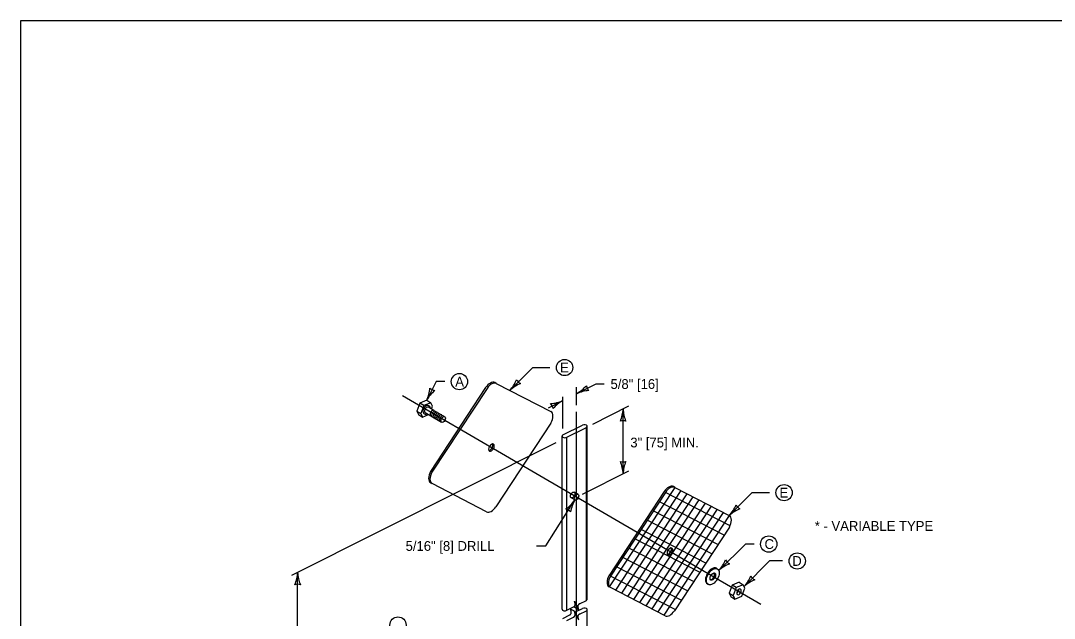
# Model space of a CAD drawing. Extents: x 49991.4 to 50021, y 49987.6 to 50011.4.
# Drawn here: x 49999.38 to 50005.73, y 49995.33 to 49999 of the extents above; entities that cross this region are included whole.
import ezdxf

# ---------------------------------------------------------------- set-up
doc = ezdxf.new("R2010")
doc.units = 0
for name, color, linetype in [('Level 1', 7, 'Continuous'), ('Level 2', 7, 'Continuous'), ('Level 25', 7, 'Continuous'), ('Level 3', 7, 'Continuous'), ('Level 4', 7, 'Continuous'), ('Level 5', 7, 'Continuous'), ('Level 6', 7, 'Continuous')]:
    doc.layers.add(name, color=color, linetype=linetype)

msp = doc.modelspace()

# ---------------------------------------------------------------- linework, layer by layer
at = {"layer": 'Level 1'}
for p, q in [((50002.2385, 49996.7445), (50001.9006, 49996.2299)), ((50002.2469, 49996.7397), (50001.9089, 49996.2251)), ((50002.3036, 49996.7701), (50002.2953, 49996.7749)), ((50002.3036, 49996.7701), (50002.6384, 49996.5971)), ((50001.8335, 49996.6484), (50001.8151, 49996.6003)), ((50001.8765, 49996.6664), (50001.8335, 49996.6484)), ((50001.8588, 49996.6336), (50001.8335, 49996.6484)), ((50001.8588, 49996.6336), (50001.8405, 49996.5855)), ((50001.9018, 49996.6516), (50001.8588, 49996.6336)), ((50001.8765, 49996.6664), (50001.9018, 49996.6516)), ((50001.921, 49996.6044), (50001.8874, 49996.6237)), ((50001.9123, 49996.6297), (50001.9018, 49996.6516)), ((50001.9059, 49996.613), (50001.9123, 49996.6297)), ((50001.921, 49996.6044), (50001.9876, 49996.5655)), ((50001.8151, 49996.6003), (50001.8256, 49996.5784)), ((50001.8151, 49996.6003), (50001.8405, 49996.5855)), ((50001.8256, 49996.5784), (50001.851, 49996.5636)), ((50001.8405, 49996.5855), (50001.851, 49996.5636)), ((50001.851, 49996.5636), (50001.887, 49996.5787)), ((50001.8666, 49996.5907), (50001.9013, 49996.5703)), ((50001.9013, 49996.5703), (50001.968, 49996.5316)), ((50002.6392, 49996.5265), (50002.3013, 49996.0119)), ((50002.7127, 49996.4535), (50002.8332, 49996.5141)), ((50002.7364, 49996.4397), (50002.857, 49996.5004)), ((50002.857, 49995.4366), (50002.857, 49996.5004)), ((50002.8619, 49995.4435), (50002.8619, 49996.5072)), ((50002.7077, 49995.3828), (50002.7077, 49996.4466)), ((50002.7364, 49995.376), (50002.7364, 49996.4397)), ((50001.9098, 49996.1545), (50001.9014, 49996.1593)), ((50002.2445, 49995.9815), (50001.9098, 49996.1545)), ((50003.3344, 49996.1056), (50002.9965, 49995.591)), ((50003.3995, 49996.1312), (50002.9979, 49995.5196)), ((50003.3428, 49996.1008), (50003.0048, 49995.5862)), ((50003.4367, 49996.112), (50003.0351, 49995.5004)), ((50003.7402, 49995.8954), (50003.3428, 49996.1008)), ((50003.3995, 49996.1312), (50003.7343, 49995.9582)), ((50003.4739, 49996.0927), (50003.0723, 49995.4812)), ((50003.5111, 49996.0735), (50003.1095, 49995.462)), ((50003.5483, 49996.0543), (50003.1467, 49995.4427)), ((50003.5855, 49996.0351), (50003.1839, 49995.4235)), ((50003.7027, 49995.8382), (50003.3052, 49996.0436)), ((50003.6227, 49996.0159), (50003.2211, 49995.4043)), ((50003.6599, 49995.9966), (50003.2583, 49995.3851)), ((50003.6651, 49995.7811), (50003.2677, 49995.9864)), ((50003.6971, 49995.9774), (50003.2955, 49995.3659)), ((50003.6276, 49995.7239), (50003.2301, 49995.9293)), ((50003.7343, 49995.9582), (50003.3327, 49995.3466)), ((50003.5901, 49995.6667), (50003.1926, 49995.8721)), ((50003.7351, 49995.8876), (50003.3972, 49995.373)), ((50003.5525, 49995.6095), (50003.155, 49995.8149)), ((50003.515, 49995.5523), (50003.1175, 49995.7577)), ((50003.4774, 49995.4952), (50003.0799, 49995.7005)), ((50003.4399, 49995.438), (50003.0424, 49995.6434)), ((50003.6549, 49995.6344), (50003.661, 49995.6309)), ((50003.4023, 49995.3808), (50003.0048, 49995.5862)), ((50003.6, 49995.5392), (50003.606, 49995.5356)), ((50003.7513, 49995.5303), (50003.733, 49995.4822)), ((50003.7943, 49995.5483), (50003.7513, 49995.5303)), ((50003.7767, 49995.5156), (50003.7513, 49995.5303)), ((50003.8197, 49995.5335), (50003.7767, 49995.5156)), ((50003.7943, 49995.5483), (50003.8197, 49995.5335)), ((50003.8302, 49995.5117), (50003.8197, 49995.5335)), ((50003.0057, 49995.5156), (50002.9973, 49995.5205)), ((50003.3404, 49995.3426), (50003.0057, 49995.5156)), ((50003.733, 49995.4822), (50003.7435, 49995.4603)), ((50003.733, 49995.4822), (50003.7584, 49995.4674)), ((50003.7767, 49995.5156), (50003.7584, 49995.4674)), ((50003.7584, 49995.4674), (50003.7689, 49995.4455)), ((50003.7689, 49995.4455), (50003.8119, 49995.4635)), ((50003.8119, 49995.4635), (50003.8302, 49995.5117)), ((50003.7435, 49995.4603), (50003.7689, 49995.4455)), ((50002.8619, 49992.2395), (50002.8619, 49995.3805))]:
    msp.add_line(p, q, dxfattribs=at)
msp.add_lwpolyline([(49999.3835, 49998.9992), (50016.7501, 49998.9992), (50016.7501, 49987.7988), (49999.3835, 49987.7988)], close=True, dxfattribs=at)
for centre, major_axis, ratio, start_param, end_param in [((50002.2657, 49996.7219), (0.0304, 0.0526), 0.57735, 0.026952, 1.471473), ((50002.2741, 49996.717), (0.0304, 0.0526), 0.57735, 0.026952, 1.471473), ((50001.8764, 49996.6076), (0.0145, 0.0251), 0.715069, 5.446271, 10.24969), ((50001.8764, 49996.6076), (0.0098, 0.0169), 0.57735, 6.151544, 9.424778), ((50001.9111, 49996.5874), (0.0098, 0.0169), 0.57735, 0.000016, 3.141596), ((50001.9207, 49996.5818), (0.0098, 0.0169), 0.57735, 0.000016, 3.141596), ((50001.9302, 49996.5763), (0.0098, 0.0169), 0.57735, 0.000016, 3.141596), ((50001.9397, 49996.5707), (0.0098, 0.0169), 0.57735, 0.000016, 3.141596), ((50001.9492, 49996.5652), (0.0098, 0.0169), 0.57735, 0.000016, 3.141596), ((50001.9587, 49996.5596), (0.0098, 0.0169), 0.57735, 0.000016, 3.141596), ((50001.9683, 49996.5541), (0.0098, 0.0169), 0.57735, 0.000016, 3.141596), ((50002.6088, 49996.544), (0.0304, 0.0526), 0.57735, 4.71239, 6.310148), ((50002.8451, 49996.5072), (0.0168, 0), 0.57735, 5.49777, 8.63937), ((50002.7245, 49996.4466), (0.0168, 0), 0.57735, 2.356185, 5.49777), ((50002.2741, 49996.3758), (0.0122, 0.0212), 0.57735, 3.153573, 9.424778), ((50002.2657, 49996.3806), (0.0122, 0.0212), 0.57735, 3.487866, 5.932002), ((50001.931, 49996.2124), (0.0304, 0.0526), 0.57735, 1.570791, 3.168563), ((50001.9393, 49996.2075), (0.0304, 0.0526), 0.57735, 1.570791, 3.168563), ((50003.3616, 49996.083), (0.0304, 0.0526), 0.57735, 0.026952, 1.471473), ((50003.37, 49996.0781), (0.0304, 0.0526), 0.57735, 0.026952, 1.471473), ((50002.2741, 49996.0346), (0.0304, 0.0526), 0.57735, 3.168548, 4.613061), ((50003.7047, 49995.9051), (0.0304, 0.0526), 0.57735, 4.71239, 6.310148), ((50003.37, 49995.7369), (0.0122, 0.0212), 0.57735, 3.153573, 9.424778), ((50003.3616, 49995.7418), (0.0122, 0.0212), 0.57735, 3.487866, 5.932002), ((50003.0269, 49995.5735), (0.0304, 0.0526), 0.57735, 1.570791, 3.168563), ((50003.6275, 49995.5868), (0.0275, 0.0476), 0.57735, 6.283184, 9.424776), ((50003.6275, 49995.5868), (0.0122, 0.0212), 0.57735, 3.391163, 6.028843), ((50003.0352, 49995.5687), (0.0304, 0.0526), 0.57735, 1.570791, 3.168563), ((50003.7943, 49995.4895), (0.0098, 0.0169), 0.57735, 3.147519, 9.423615), ((50003.78, 49995.4976), (0.0098, 0.0169), 0.57735, 3.961375, 5.478491), ((50003.7749, 49995.5008), (0.0098, 0.0169), 0.57735, 4.589945, 4.829787), ((50003.37, 49995.3957), (0.0304, 0.0526), 0.57735, 3.168548, 4.613061)]:
    msp.add_ellipse(centre, major_axis=major_axis, ratio=ratio, start_param=start_param, end_param=end_param, dxfattribs=at)
for centre, major_axis in [((50001.9778, 49996.5485), (0.0098, 0.0169)), ((50002.7967, 49996.0713), (0.0098, 0.0169)), ((50003.6335, 49995.5833), (0.0275, 0.0476)), ((50003.6335, 49995.5833), (0.0122, 0.0212))]:
    msp.add_ellipse(centre, major_axis=major_axis, ratio=0.57735, dxfattribs=at)
at = {"layer": 'Level 2'}
for centre in [(50002.7233, 49996.868), (50002.0775, 49996.7813), (50004.0709, 49996.099), (50003.9764, 49995.7831), (50004.1517, 49995.6792), (50001.7003, 49995.2856)]:
    msp.add_circle(centre, 0.05, dxfattribs=at)
at = {"layer": 'Level 25'}
for p, q in [((50002.7967, 49996.7072), (50002.881, 49996.7496)), ((50002.7967, 49996.7072), (50002.86, 49996.7391)), ((50003.3995, 49996.1312), (50003.3912, 49996.136)), ((50003.661, 49995.6309), (50003.6549, 49995.6344)), ((50003.606, 49995.5356), (50003.6, 49995.5392)), ((50002.7967, 49995.3434), (50002.7967, 49995.4063))]:
    msp.add_line(p, q, dxfattribs=at)
at = {"layer": 'Level 3'}
for p, q in [((50002.7967, 49996.6357), (50002.7967, 49996.7472)), ((50002.7126, 49996.4935), (50002.7126, 49996.6873)), ((50002.6244, 49996.6206), (50002.7126, 49996.665)), ((50002.8976, 49996.5208), (50003.1183, 49996.6317)), ((50003.0825, 49996.215), (50003.0825, 49996.6137)), ((50001.0489, 49995.5917), (50002.6719, 49996.4074)), ((50002.8322, 49996.0892), (50003.1183, 49996.233)), ((50001.084, 49993.6606), (50001.084, 49995.6093))]:
    msp.add_line(p, q, dxfattribs=at)
for points in [[(50002.3867, 49996.7271), (50002.528, 49996.8684), (50002.6333, 49996.8681)], [(50001.9875, 49996.7813), (50001.9346, 49996.7813), (50001.8765, 49996.6664)], [(50002.9652, 49996.7665), (50002.9147, 49996.7665), (50002.7967, 49996.7072)], [(50003.7343, 49995.9582), (50003.8757, 49996.0995), (50003.9809, 49996.0992)], [(50002.5503, 49995.7715), (50002.6077, 49995.7715), (50002.7866, 49996.0541)], [(50003.8864, 49995.7831), (50003.833, 49995.7831), (50003.67, 49995.6198)], [(50004.0617, 49995.6792), (50003.9806, 49995.6792), (50003.8254, 49995.5216)]]:
    msp.add_lwpolyline(points, dxfattribs=at)
for centre, radius, start, end in [((50001.6636, 49996.7612), 0.233, 335.98356, 355.23341), ((50001.9344, 49996.7808), 0.0548, 225.29506, 261.01742), ((50002.214, 49996.8836), 0.233, 317.82762, 337.07747), ((50002.5373, 49996.5636), 0.2223, 112.45632, 132.63983), ((50002.4773, 49996.8178), 0.0548, 207.13913, 242.86149), ((50002.6819, 49996.91), 0.233, 299.50928, 318.75913), ((50002.9112, 49996.7648), 0.0548, 188.82079, 224.54315), ((50002.0705, 49996.5579), 0.2223, 130.61226, 150.79576), ((50002.8882, 49996.5046), 0.2223, 94.13798, 114.32149), ((50002.621, 49996.8676), 0.2223, 274.13774, 294.32125), ((50002.598, 49996.6074), 0.0548, 8.82055, 44.54291), ((50002.8274, 49996.4622), 0.233, 119.50904, 138.75889), ((50002.8604, 49996.6229), 0.2223, 337.45601, 357.63952), ((50003.3152, 49996.6252), 0.233, 182.82731, 202.07716), ((50003.0825, 49996.4855), 0.0548, 72.13882, 107.86118), ((50003.0825, 49996.3432), 0.0548, 252.13882, 287.86118), ((50002.8498, 49996.2035), 0.233, 2.82731, 22.07716), ((50003.3047, 49996.2058), 0.2223, 157.45601, 177.63952), ((50002.6038, 49996.1806), 0.2223, 305.11813, 325.30164), ((50002.9893, 49995.9393), 0.233, 150.48943, 169.73928), ((50002.718, 49995.9458), 0.0548, 39.80094, 75.5233), ((50003.5616, 49996.1146), 0.233, 317.82762, 337.07747), ((50003.8849, 49995.7947), 0.2223, 112.45632, 132.63983), ((50003.825, 49996.0489), 0.0548, 207.13913, 242.86149), ((50003.4972, 49995.776), 0.233, 317.89858, 337.14843), ((50003.8208, 49995.4564), 0.2223, 112.52728, 132.71078), ((50003.7606, 49995.7105), 0.0548, 207.21008, 242.93245), ((50000.8619, 49995.6185), 0.2223, 337.45601, 357.63952), ((50001.3167, 49995.6208), 0.233, 182.82731, 202.07716), ((50003.6515, 49995.6766), 0.233, 318.28139, 337.53124), ((50003.9154, 49995.6129), 0.0548, 207.5929, 243.31526), ((50001.084, 49995.4811), 0.0548, 72.13882, 107.86118), ((50003.9773, 49995.3592), 0.2223, 112.91009, 133.0936)]:
    msp.add_arc(centre, radius, start, end, dxfattribs=at)
at = {"layer": 'Level 4'}
for p, q in [((50002.8064, 49996.0884), (50002.7827, 49996.1022)), ((50002.7866, 49996.0541), (50002.7629, 49996.0679))]:
    msp.add_line(p, q, dxfattribs=at)
msp.add_ellipse((50002.7728, 49996.085), major_axis=(0.0099, 0.0172), ratio=0.57735, dxfattribs=at)
at = {"layer": 'Level 5'}
for p, q in [((50002.571, 49996.2027), (50001.728, 49996.6942)), ((50002.7967, 49992.3661), (50002.7967, 49996.5957)), ((50003.9286, 49995.4112), (50002.571, 49996.2027))]:
    msp.add_line(p, q, dxfattribs=at)
at = {"layer": 'Level 6'}
for p, q in [((50002.7364, 49995.376), (50002.7787, 49995.3973)), ((50002.7822, 49995.4004), (50002.7855, 49995.3935)), ((50002.784, 49995.4328), (50002.8093, 49995.3798)), ((50002.814, 49995.4151), (50002.857, 49995.4366)), ((50002.7126, 49995.3268), (50002.755, 49995.3481)), ((50002.7364, 49995.3131), (50002.7787, 49995.3344)), ((50002.784, 49995.3699), (50002.7603, 49995.3836)), ((50002.784, 49995.3699), (50002.8093, 49995.3169)), ((50002.8093, 49995.3798), (50002.7855, 49995.3935)), ((50002.7903, 49995.3658), (50002.8332, 49995.3874)), ((50002.814, 49995.3521), (50002.857, 49995.3737))]:
    msp.add_line(p, q, dxfattribs=at)
for centre, start_param, end_param in [((50002.8451, 49995.4435), 5.49777, 6.283186), ((50002.7245, 49995.3829), 3.146891, 5.49777), ((50002.8451, 49995.3805), 5.49777, 8.63937)]:
    msp.add_ellipse(centre, major_axis=(0.0168, 0), ratio=0.57735, start_param=start_param, end_param=end_param, dxfattribs=at)
for points in [[(50002.7787, 49995.3973), (50002.7859, 49995.4009), (50002.7891, 49995.416), (50002.784, 49995.4328)], [(50002.814, 49995.4151), (50002.8067, 49995.4118), (50002.8029, 49995.3968), (50002.8093, 49995.3798)], [(50002.755, 49995.3481), (50002.7622, 49995.3517), (50002.7653, 49995.3668), (50002.7603, 49995.3836)], [(50002.7787, 49995.3344), (50002.7859, 49995.338), (50002.7891, 49995.3531), (50002.784, 49995.3699)], [(50002.7903, 49995.3658), (50002.7891, 49995.3653), (50002.7881, 49995.3645), (50002.7871, 49995.3634)], [(50002.814, 49995.3521), (50002.8067, 49995.3488), (50002.8029, 49995.3339), (50002.8093, 49995.3169)]]:
    msp.add_open_spline(points, degree=2, dxfattribs=at)

# ---------------------------------------------------------------- texts
at = {"layer": 'Level 2'}
for s, p in [('E', (50002.6953, 49996.838)), ('A', (50002.0517, 49996.7513)), ('5/8" [16]', (50003.0052, 49996.7365)), ('3" [75] MIN.', (50003.1267, 49996.3771)), ('E', (50004.0429, 49996.069)), ('* - VARIABLE TYPE', (50004.2594, 49995.8644)), ('5/16" [8] DRILL', (50001.7471, 49995.7415)), ('C', (50003.9509, 49995.7531)), ('D', (50004.1213, 49995.6492))]:
    msp.add_text(s, height=0.06, dxfattribs=at).set_placement(p)
at = {"layer": 'Level 25'}
msp.add_text('R. W. Schultz  December 16, 1997', height=0.00000226, rotation=329.75191, dxfattribs=at).set_placement((50003.7845, 49995.4726))

doc.saveas('drawing.dxf')
